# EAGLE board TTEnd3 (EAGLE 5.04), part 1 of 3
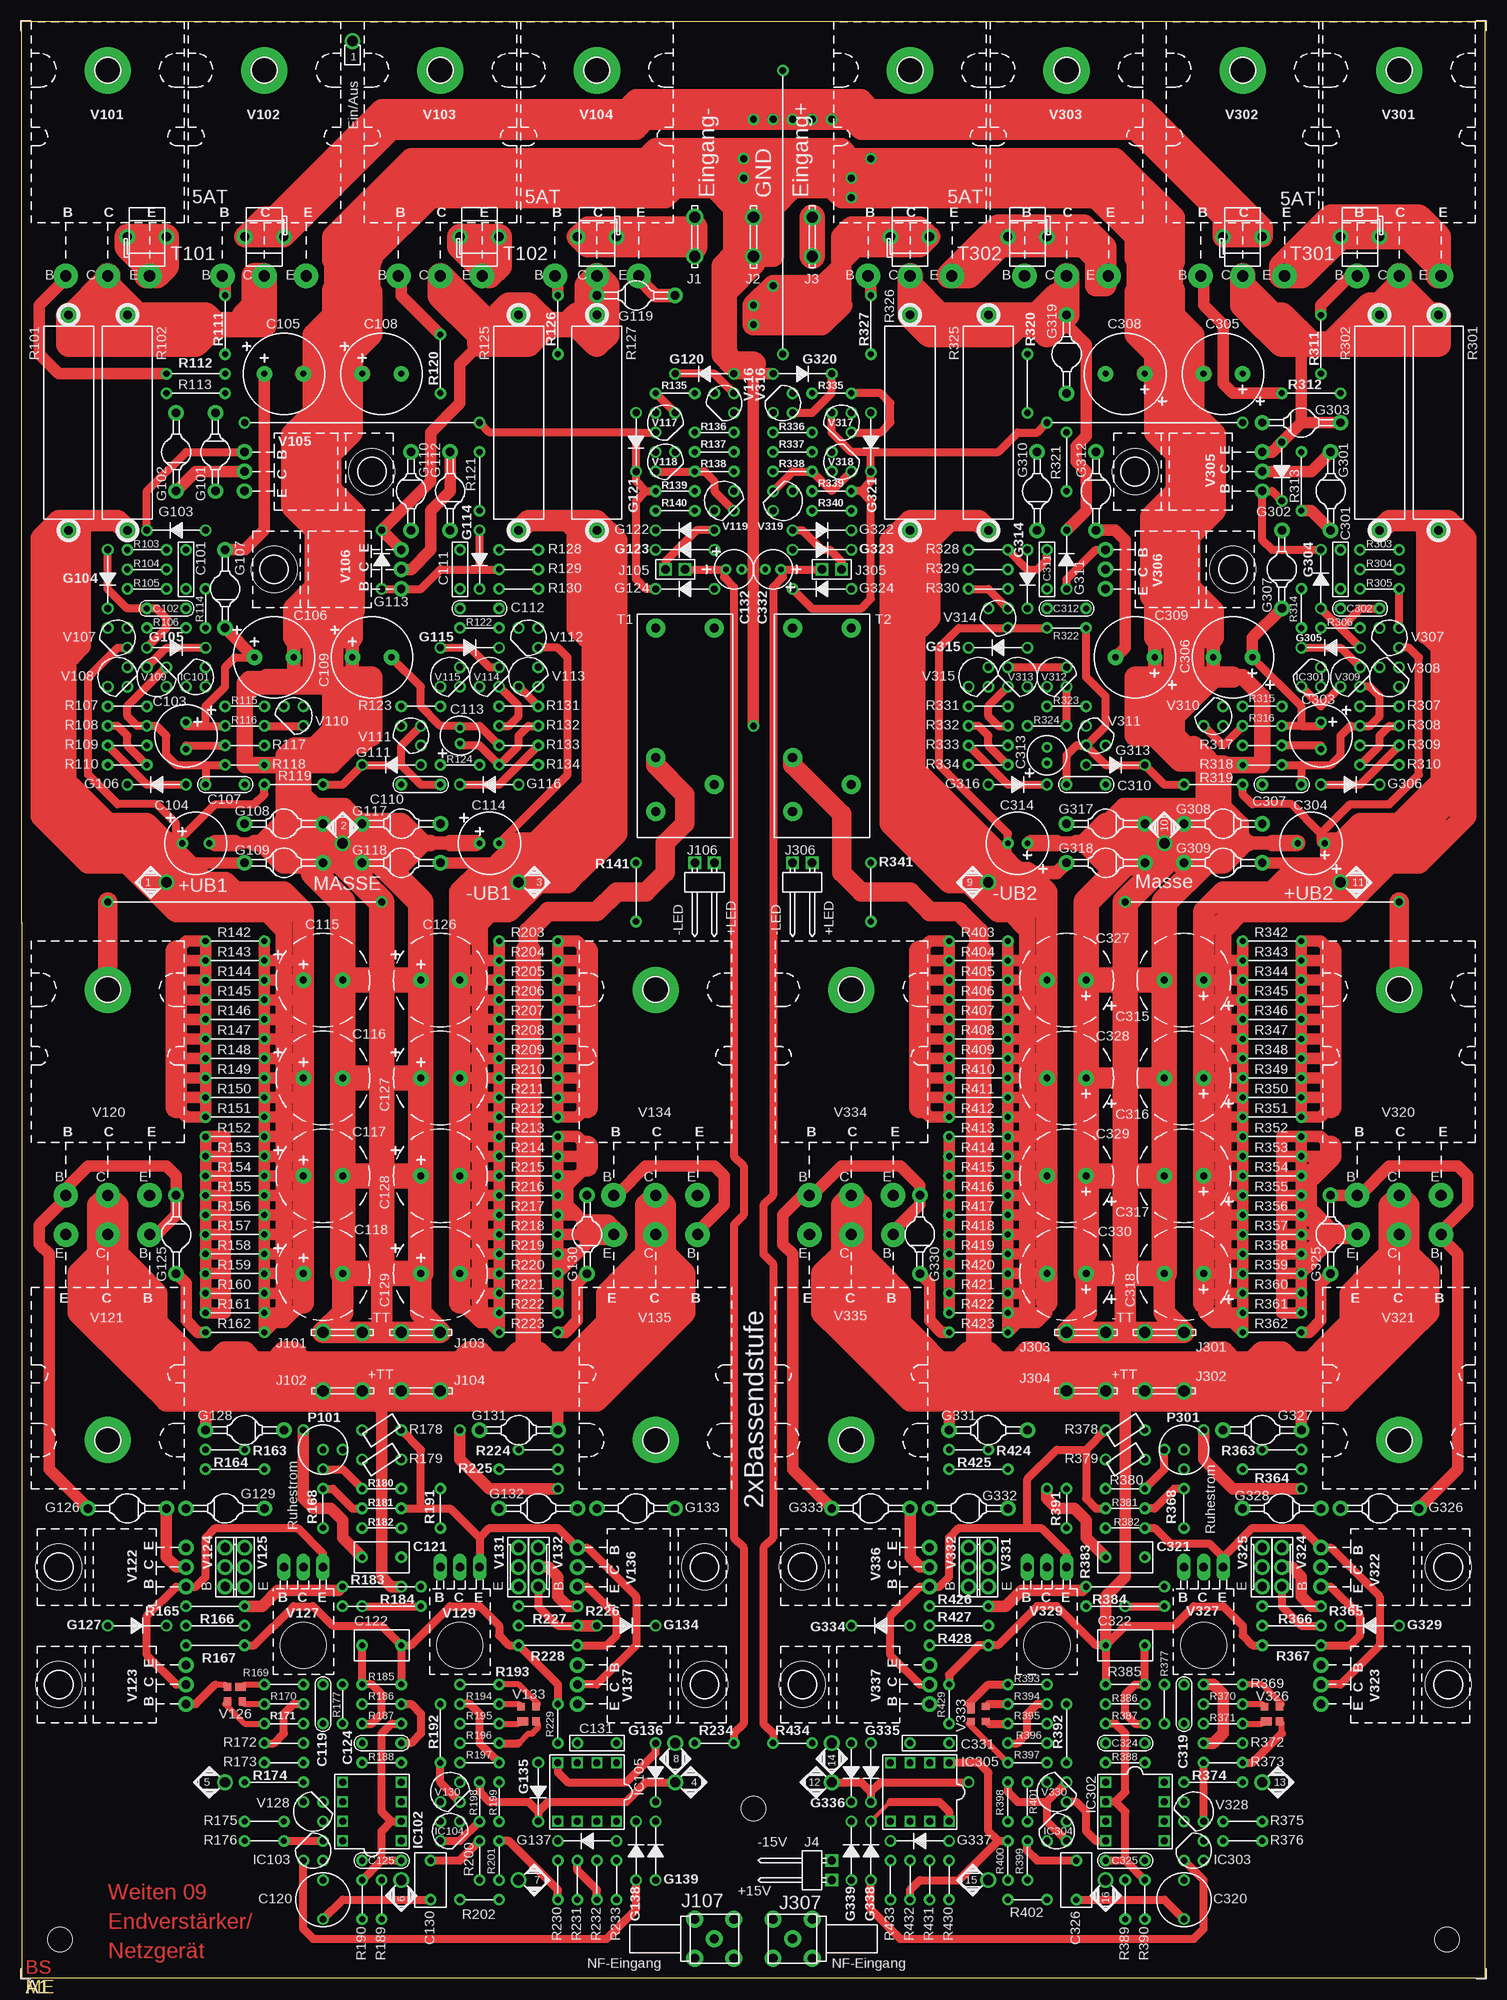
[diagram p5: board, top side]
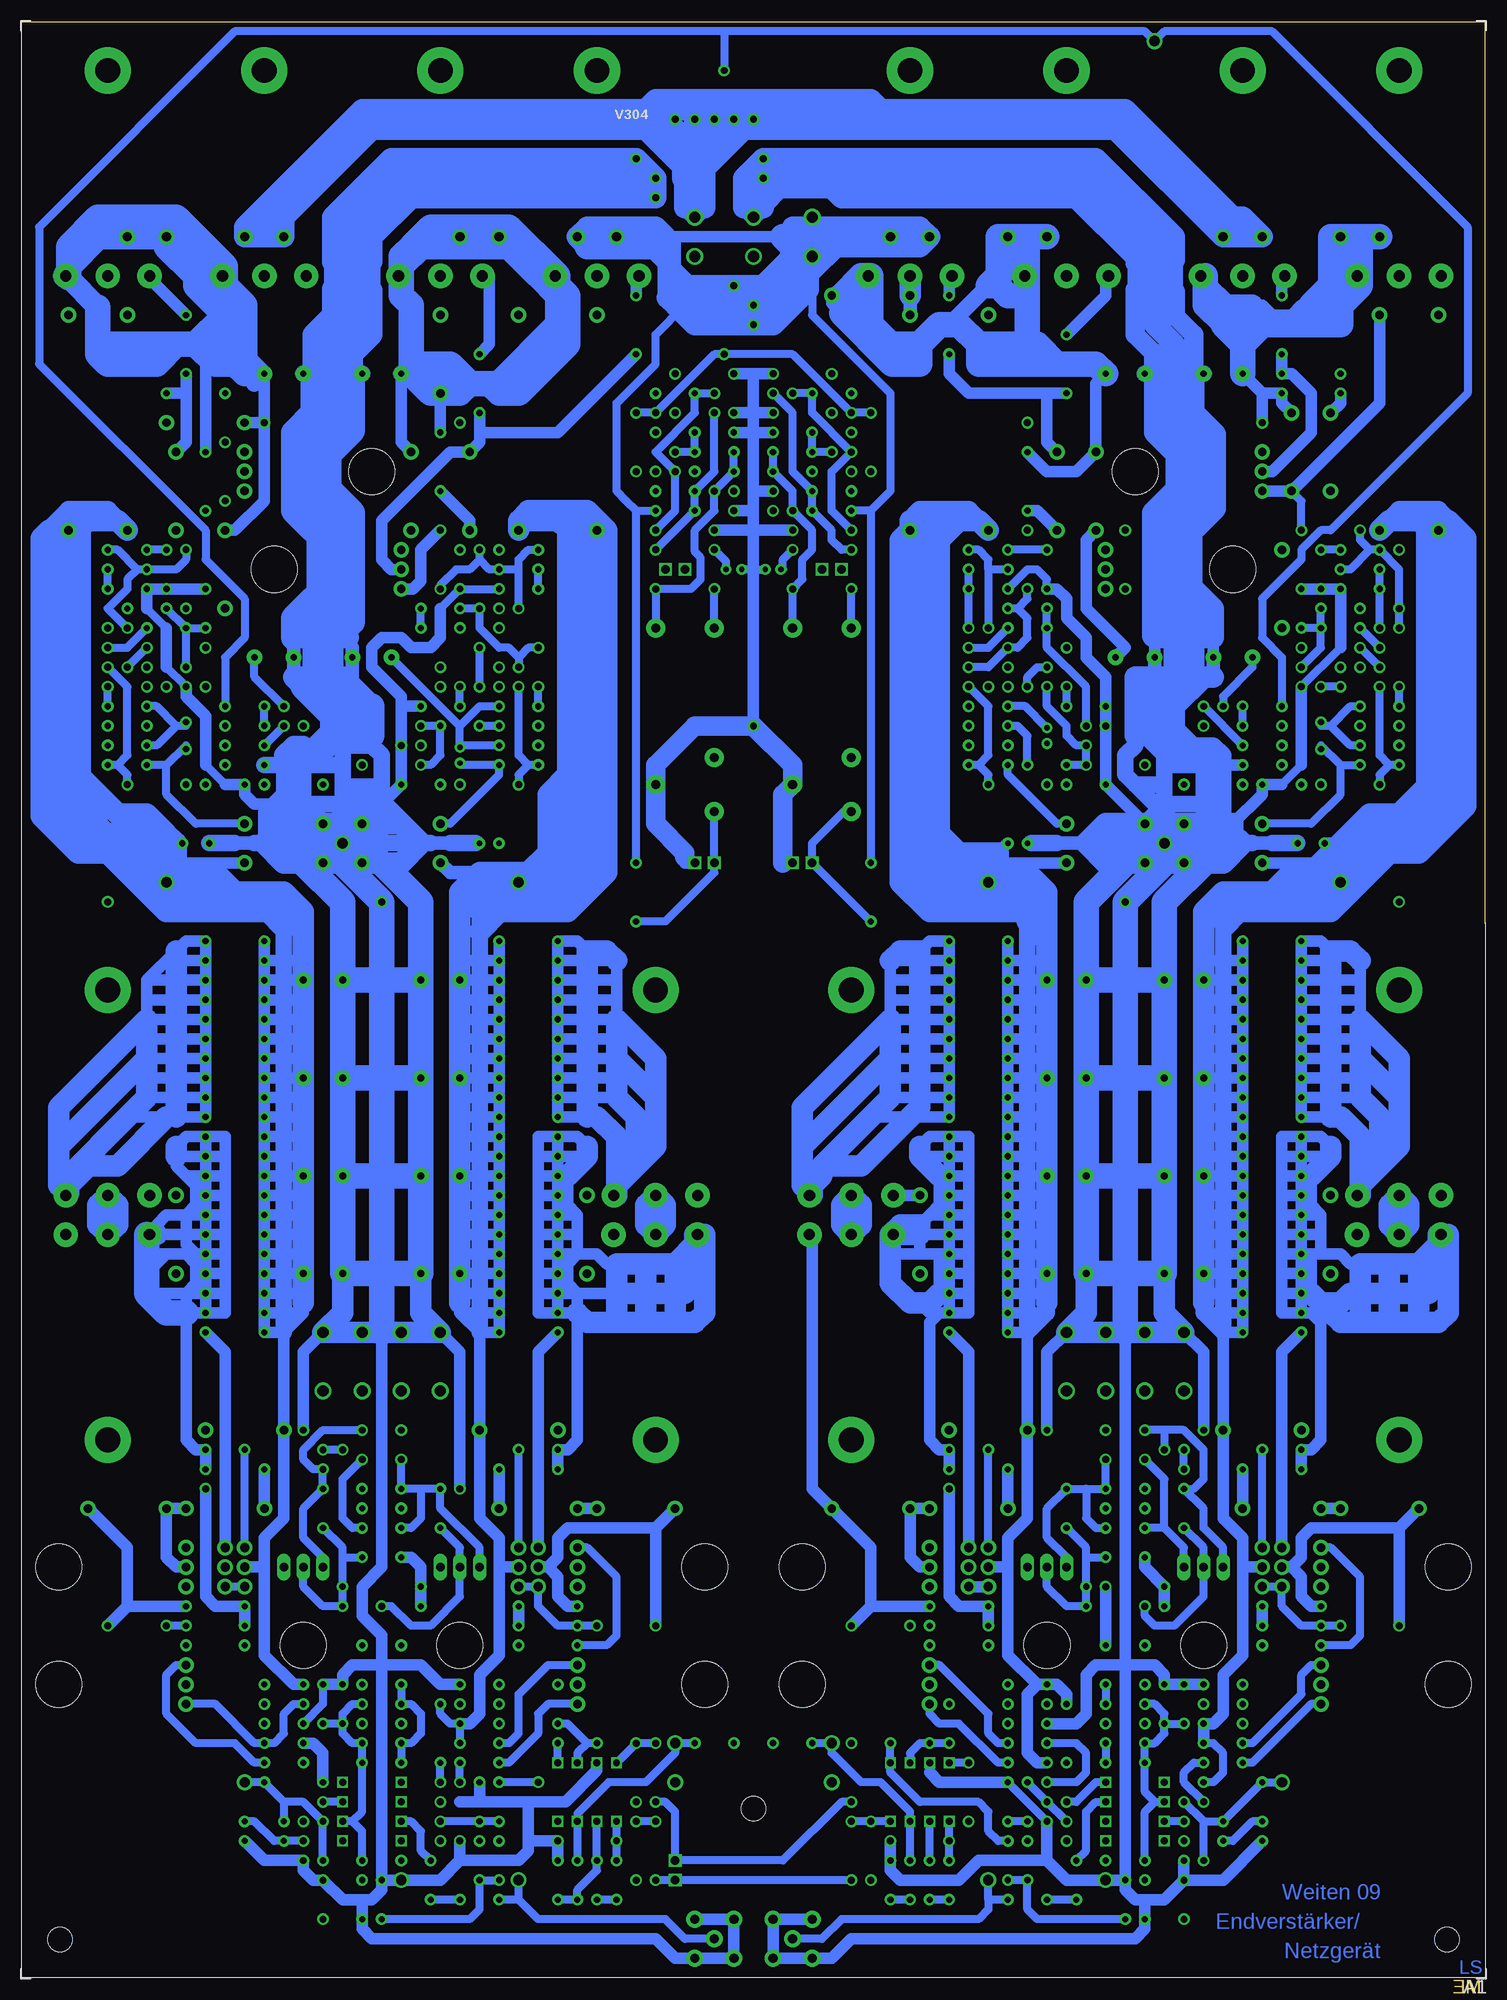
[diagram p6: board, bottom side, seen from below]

Size 190 x 254 mm. Coordinates in mm from the lower left corner, seen from the top.
Outline: 190,137.78 190,0 0,0 0,137.02
Outline: 190,137.16 190,254 0,254 0,136.91
Copper layers (1*16): Oben/V2 0.035mm / dielectric 1.5mm / Unten/V1 0.035mm
Design rules "default": minimum track width 8mil, minimum drill 24mil, track to track 20mil, track to pad 20mil, pad to pad 20mil, via to via 20mil, smd to smd 20mil, copper to edge 20mil, drill to drill 20mil, minimum pad ring 10mil, minimum via ring 8mil, stop-mask expansion 5mil, vias tented up to drill 0mil, thermal gap 10mil
Holes 6 mm at 185.17,53.34 101.35,53.34 4.83,53.34 88.65,53.34 101.35,38.1 88.65,38.1 185.17,38.1 4.83,38.1 45.47,195.58 32.77,182.88 144.53,195.58 157.23,182.88

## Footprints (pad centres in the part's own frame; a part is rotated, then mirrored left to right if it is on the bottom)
M05T2,5 = drill 0.8 pad 1.499 round: 1 -2.54,0; 2 2.54,0
K5 = drill 0.8 pad 1.499 round: 1 -2.54,0; 2 2.54,0
E3,5S08 = drill 0.8 pad 1.499 round: 1 -1.753,0; 2 1.753,0
E05S10,5 = drill 0.8 pad 2.007 round: 1 -2.54,0; 2 2.54,0
E2,0S05 = drill 0.7 pad 1.397 round: 1 -1.016,0; 2 1.016,0
E2,5S08@1 = drill 0.7 pad 1.499 round: 1 -1.27,0; 2 1.27,0
E05S12,7U = drill 0.9 pad 2.007 round: 1 -2.54,0; 2 2.54,0
KP5/7 = drill 0.9 pad 1.499 round: 1 -2.54,0; 2 2.54,0
M05T4,5 = drill 0.8 pad 1.499 round: 1 -2.54,0; 2 2.54,0
E2,5S08 = drill 0.7 pad 1.499 round: 1 -1.27,0; 2 1.27,0
LÖTFA = drill 1.35 pad 2.032 round: 1 0,0
SOD-57 = drill 1.1 pad 2.007 round: 1 -5.08,0; 2 5.08,0
DIO7-5 = drill 0.9 pad 1.499 round: 1 -2.54,0; 2 5.08,0
TO-92/BC = drill 0.9 pad 1.499 round: 1 1.27,1.27; 2 1.27,-1.27; 3 -1.27,-1.27
DIL-8 = drill 0.9 pad 1.397 square: 1 0,0; 2 2.54,0; 3 5.08,0; 4 7.62,0; 5 7.62,7.62; 6 5.08,7.62; 7 2.54,7.62; 8 0,7.62
FLACH6,3 = drill 1.45 pad 2.184 round: 1 -2.54,0; 2 2.54,0
BERG02SW = drill 1.1 pad 1.499 square: 1 0,0; 2 0,2.54
BERG02SG = drill 1.1 pad 1.499 square: 1 0,0; 2 2.54,0
SMBR665 = drill 1.2 pad 2.184 round: 1 0,0; 2 -2.54,2.54; 3 -2.54,-2.54; 4 2.54,-2.54; 5 2.54,2.54
MESSPU/R = drill 1.35 pad 2.007 round: 1 0,0
T82P = drill 0.9 pad 1.499 round: 1 -2.54,0; 2 0,2.54; S 0,0
R27,5 = drill 1.1 pad 2.007 round: 1 -12.7,0; 2 15.24,0
R5 = drill 0.8 pad 1.499 round: 1 -2.54,0; 2 2.54,0
R7,5 = drill 0.8 pad 1.499 round: 1 -3.81,0; 2 3.81,0
NTC5,0B = drill 0.9 pad 1.499 round: 1 -2.54,0; 2 2.54,0
R10 = drill 0.8 pad 1.499 round: 1 -5.08,0; 2 5.08,0
TYCORT314 = drill 1.2 pad 2.489 round: 11 7.62,2.54; 12 4.12,-5.08; 14 11.12,-5.08; A1 -12.7,-5.08; A2 -12.7,2.54
SICH5*20 = drill 1.2 pad 2.032 round: 1 -10.16,0; 2 -5.08,0; 3 5.08,0; 4 10.16,0
M3 = hole 3.2: 0,0
TO-264/LU = drill 1.45 pad 3.175 round: 1 -5.45,0; 2 0,0; 3 5.43,0
TO-220/LU = drill 1.1 pad 2.007 round: 1 -2.54,0; 2 0,0; 3 2.54,0
TO-92 = drill 0.9 pad 1.499 round: 1 -1.27,-1.27; 2 1.27,-1.27; 3 1.27,1.27
SOT-54 = drill 0.9 pad 1.499 round: B 1.27,-1.27; C 1.27,1.27; E -1.27,1.27
TO-126/S = drill 1.2 pad 2.007 round: 1 -2.54,0; 2 0,0; 3 2.54,0
SOT143 = smd 1.397 x 1.016: 1 0.737,0.965 | smd 0.94 x 1.016: 2 -0.965,0.965; 3 -0.965,-0.94; 4 0.965,-0.94
TO-126/LU = drill 1.1 pad 1.778 long: 1 -2.54,0; 2 0,0; 3 2.54,0 | hole 6: 0,10.16

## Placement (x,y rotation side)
C101  22n/63  [M05T2,5]  21.34,182.88 270 top
C102  12p  [K5]  18.8,177.8 0 top
C103  220µ/25  [E3,5S08]  21.34,161.29 270 top
C104  47µ/63  [E3,5S08]  22.61,147.32 0 top
C105  100µ/63  [E05S10,5]  34.04,208.28 0 top
C106  100µ/63  [E05S10,5]  32.77,171.45 0 top
C107  10n  [K5]  26.42,154.94 0 top
C108  100µ/63  [E05S10,5]  46.74,208.28 0 top
C109  100µ/63  [E05S10,5]  45.47,171.45 0 top
C110  1,5n  [K5]  51.82,154.94 0 top
C111  10n  [M05T2,5]  56.9,182.88 90 top
C112  12p  [K5]  59.44,177.8 0 top
C113  10µ/100  [E2,0S05]  56.9,161.29 90 top
C114  47µ/63  [E2,5S08@1]  60.71,147.32 0 top
C115  470µ/63  [E05S12,7U]  39.12,129.54 0 top
C116  470µ/63  [E05S12,7U]  39.12,116.84 0 top
C117  470µ/63  [E05S12,7U]  39.12,104.14 0 top
C118  470µ/63  [E05S12,7U]  39.12,91.44 0 top
C119  1n/63  [K5]  39.12,35.56 270 top
C120  270p  [KP5/7]  39.12,10.16 90 top
C121  220p/250  [M05T4,5]  46.74,54.61 0 top
C122  330n/50  [M05T4,5]  46.74,43.18 180 top
C124  82p/100  [K5]  46.74,30.48 0 top
C125  27p  [K5]  46.74,15.24 0 top
C126  470µ/63  [E05S12,7U]  54.36,129.54 0 top
C127  470µ/63  [E05S12,7U]  54.36,116.84 0 top
C128  470µ/63  [E05S12,7U]  54.36,104.14 0 top
C129  470µ/63  [E05S12,7U]  54.36,91.44 0 top
C130  220n/63  [M05T4,5]  53.09,12.7 90 top
C131  100n/63  [M05T2,5]  74.68,30.48 0 top
C132  10µ/100  [E2,0S05]  92.46,182.88 0 top
C301  22n/63  [M05T2,5]  171.2,182.88 270 top
C302  12p  [K5]  173.74,177.8 180 top
C303  220µ/25  [E3,5S08]  168.66,161.29 270 top
C304  47µ/63  [E3,5S08]  167.39,147.32 180 top
C305  100µ/63  [E05S10,5]  155.96,208.28 180 top
C306  100µ/63  [E05S10,5]  157.23,171.45 180 top
C307  10n  [K5]  163.58,154.94 180 top
C308  100µ/63  [E05S10,5]  143.26,208.28 180 top
C309  100µ/63  [E05S10,5]  144.53,171.45 180 top
C310  1,5n  [K5]  138.18,154.94 180 top
C311  10n  [M05T2,5]  133.1,182.88 90 top
C312  12p  [K5]  135.64,177.8 180 top
C313  10µ/100  [E2,0S05]  133.1,158.75 90 top
C314  47µ/63  [E2,5S08]  129.29,147.32 180 top
C315  470µ/63  [E05S12,7U]  150.88,129.54 180 top
C316  470µ/63  [E05S12,7U]  150.88,116.84 180 top
C317  470µ/63  [E05S12,7U]  150.88,104.14 180 top
C318  470µ/63  [E05S12,7U]  150.88,91.44 180 top
C319  330p  [K5]  150.88,35.56 270 top
C320  270p  [KP5/7]  150.88,10.16 90 top
C321  220p/250  [M05T4,5]  143.26,54.61 0 top
C322  330n  [M05T4,5]  143.26,43.18 0 top
C324  82p/100  [K5]  143.26,30.48 180 top
C325  27p  [K5]  143.26,15.24 180 top
C326  220n/63  [M05T4,5]  136.91,12.7 90 top
C327  470µ/63  [E05S12,7U]  135.64,129.54 180 top
C328  470µ/63  [E05S12,7U]  135.64,116.84 180 top
C329  470µ/63  [E05S12,7U]  135.64,104.14 180 top
C330  470µ/63  [E05S12,7U]  135.64,91.44 180 top
C331  100n/63  [M05T2,5]  117.86,30.48 0 top
C332  10µ/100  [E2,0S05]  97.54,182.88 180 top
EIN1  1  [LÖTFA]  42.93,251.46 90 top
G101  BYV27  [SOD-57]  25.15,198.12 90 top
G102  BYV27  [SOD-57]  20.07,198.12 270 top
G103  1N4148  [DIO7-5]  21.34,187.96 180 top
G104  1N4148  [DIO7-5]  11.18,182.88 270 top
G105  1N4148  [DIO7-5]  18.8,172.72 0 top
G106  1N4148  [DIO7-5]  18.8,154.94 180 top
G107  BYV27  [SOD-57]  26.42,180.34 270 top
G108  BYV27  [SOD-57]  34.04,149.86 180 top
G109  BYV27  [SOD-57]  34.04,144.78 180 top
G110  BYV27  [SOD-57]  50.55,193.04 90 top
G111  1N4148  [DIO7-5]  49.28,157.48 180 top
G112  BYV27  [SOD-57]  55.63,193.04 270 top
G113  1N4148  [DIO7-5]  46.74,182.88 90 top
G114  1N4148  [DIO7-5]  59.44,185.42 270 top
G115  1N4148  [DIO7-5]  56.9,172.72 0 top
G116  1N4148  [DIO7-5]  61.98,154.94 180 top
G117  BYV27  [SOD-57]  49.28,149.86 180 top
G118  BYV27  [SOD-57]  49.28,144.78 180 top
G119  BYV27  [SOD-57]  79.76,218.44 180 top
G120  1N4148  [DIO7-5]  89.92,208.28 180 top
G121  1N4148  [DIO7-5]  79.76,200.66 270 top
G122  1N4148  [DIO7-5]  87.38,187.96 180 top
G123  1N4148  [DIO7-5]  87.38,185.42 180 top
G124  1N4148  [DIO7-5]  87.38,180.34 180 top
G125  BYV27  [SOD-57]  20.07,96.52 90 top
G126  BYV27  [SOD-57]  13.72,60.96 0 top
G127  BAT41  [DIO7-5]  13.72,45.72 0 top
G128  BYV27  [SOD-57]  28.96,71.12 0 top
G129  BYV27  [SOD-57]  26.42,60.96 180 top
G130  BYV27  [SOD-57]  73.41,96.52 270 top
G131  BYV27  [SOD-57]  64.52,71.12 0 top
G132  BYV27  [SOD-57]  67.06,60.96 180 top
G133  BYV27  [SOD-57]  79.76,60.96 0 top
G134  BAT41  [DIO7-5]  77.22,45.72 0 top
G135  1N4148  [DIO7-5]  67.06,25.4 270 top
G136  1N4148  [DIO7-5]  82.3,27.94 270 top
G137  1N4148  [DIO7-5]  74.68,17.78 180 top
G138  1N4148  [DIO7-5]  79.76,15.24 90 top
G139  1N4148  [DIO7-5]  82.3,15.24 90 top
G301  BYV27  [SOD-57]  169.93,193.04 90 top
G302  1N4148  [DIO7-5]  163.58,196.85 270 top
G303  BYV27  [SOD-57]  166.12,201.93 180 top
G304  1N4148  [DIO7-5]  168.66,180.34 90 top
G305  1N4148  [DIO7-5]  171.2,172.72 180 top
G306  1N4148  [DIO7-5]  171.2,154.94 0 top
G307  BYV27  [SOD-57]  163.58,182.88 270 top
G308  BYV27  [SOD-57]  155.96,149.86 0 top
G309  BYV27  [SOD-57]  155.96,144.78 0 top
G310  BYV27  [SOD-57]  131.83,193.04 270 top
G311  1N4148  [DIO7-5]  135.64,182.88 90 top
G312  BYV27  [SOD-57]  139.45,193.04 90 top
G313  1N4148  [DIO7-5]  140.72,157.48 0 top
G314  1N4148  [DIO7-5]  130.56,182.88 270 top
G315  1N4148  [DIO7-5]  128.02,172.72 180 top
G316  1N4148  [DIO7-5]  128.02,154.94 0 top
G317  BYV27  [SOD-57]  140.72,149.86 0 top
G318  BYV27  [SOD-57]  140.72,144.78 0 top
G319  BYV27  [SOD-57]  135.64,210.82 90 top
G320  1N4148  [DIO7-5]  100.08,208.28 0 top
G321  1N4148  [DIO7-5]  110.24,200.66 270 top
G322  1N4148  [DIO7-5]  102.62,187.96 0 top
G323  1N4148  [DIO7-5]  102.62,185.42 0 top
G324  1N4148  [DIO7-5]  105.16,180.34 180 top
G325  BYV27  [SOD-57]  169.93,96.52 90 top
G326  BYV27  [SOD-57]  176.28,60.96 180 top
G327  BYV27  [SOD-57]  161.04,71.12 180 top
G328  BYV27  [SOD-57]  163.58,60.96 0 top
G329  BAT41  [DIO7-5]  176.28,45.72 180 top
G330  BYV27  [SOD-57]  116.59,96.52 270 top
G331  BYV27  [SOD-57]  125.48,71.12 180 top
G332  BYV27  [SOD-57]  122.94,60.96 0 top
G333  BYV27  [SOD-57]  110.24,60.96 180 top
G334  BAT41  [DIO7-5]  112.78,45.72 180 top
G335  1N4148  [DIO7-5]  110.24,27.94 270 top
G336  1N4148  [DIO7-5]  107.7,27.94 270 top
G337  1N4148  [DIO7-5]  117.86,17.78 180 top
G338  1N4148  [DIO7-5]  110.24,15.24 90 top
G339  1N4148  [DIO7-5]  107.7,15.24 90 top
IC101  TL431  [TO-92/BC]  22.61,168.91 0 top
IC102  OPA134  [DIL-8]  49.28,17.78 90 top
IC103  TL431  [TO-92/BC]  37.85,16.51 0 top
IC104  TL431  [TO-92/BC]  55.63,19.05 180 top
IC105  TL062  [DIL-8]  77.22,27.94 180 top
IC301  TL431  [TO-92/BC]  167.39,168.91 0 top
IC302  OPA134  [DIL-8]  140.72,25.4 270 top
IC303  TL431  [TO-92/BC]  152.15,16.51 0 top
IC304  TL431  [TO-92/BC]  134.37,19.05 0 top
IC305  TL062  [DIL-8]  120.4,27.94 180 top
J1  FLACH6,3  [FLACH6,3]  87.38,226.06 270 top
J2  FLACH6,3  [FLACH6,3]  95,226.06 90 top
J3  FLACH6,3  [FLACH6,3]  102.62,226.06 270 top
J4  BERG02SW  [BERG02SW]  105.16,12.7 0 top
J101  FLACH6,3  [FLACH6,3]  41.66,83.82 0 top
J102  FLACH6,3  [FLACH6,3]  41.66,76.2 180 top
J103  FLACH6,3  [FLACH6,3]  51.82,83.82 0 top
J104  FLACH6,3  [FLACH6,3]  51.82,76.2 180 top
J105  BERG02SG  [BERG02SG]  86.11,182.88 180 top
J106  BERG02SW  [BERG02SW]  89.92,144.78 90 top
J107  SMB  [SMBR665]  89.92,5.08 180 top
J301  FLACH6,3  [FLACH6,3]  148.34,83.82 180 top
J302  FLACH6,3  [FLACH6,3]  148.34,76.2 0 top
J303  FLACH6,3  [FLACH6,3]  138.18,83.82 0 top
J304  FLACH6,3  [FLACH6,3]  138.18,76.2 0 top
J305  BERG02SG  [BERG02SG]  103.89,182.88 0 top
J306  BERG02SW  [BERG02SW]  102.62,144.78 90 top
J307  SMB  [SMBR665]  100.08,5.08 0 top
MP1  1  [MESSPU/R]  18.8,142.24 0 top
MP2  3  [MESSPU/R]  64.52,142.24 180 top
MP3  2  [MESSPU/R]  41.66,147.32 270 top
MP4  9  [MESSPU/R]  125.48,142.24 0 top
MP5  10  [MESSPU/R]  148.34,147.32 270 top
MP6  11  [MESSPU/R]  171.2,142.24 180 top
MP7  7  [MESSPU/R]  64.52,12.7 180 top
MP8  15  [MESSPU/R]  125.48,12.7 0 top
MP9  13  [MESSPU/R]  161.04,25.4 180 top
MP10  12  [MESSPU/R]  105.16,25.4 0 top
MP11  5  [MESSPU/R]  26.42,25.4 0 top
MP12  4  [MESSPU/R]  84.84,25.4 180 top
MP13  6  [MESSPU/R]  49.28,12.7 90 top
MP14  16  [MESSPU/R]  140.72,12.7 90 top
MP15  8  [MESSPU/R]  84.84,30.48 90 top
MP16  14  [MESSPU/R]  105.16,30.48 90 top
P101  500  [T82P]  39.12,68.58 180 top
P301  500  [T82P]  150.88,68.58 90 top
R101  0,1  [R27,5]  6.1,203.2 270 top
R102  0,1  [R27,5]  13.72,203.2 270 top
R103  220  [R5]  16.26,185.42 0 top
R104  430  [R5]  16.26,182.88 180 top
R105  18k  [R5]  16.26,180.34 0 top
R106  39k  [R5]  18.8,175.26 0 top
R107  100  [R5]  13.72,165.1 180 top
R108  33k  [R5]  13.72,162.56 0 top
R109  510  [R5]  13.72,160.02 180 top
R110  8,2k  [R5]  13.72,157.48 0 top
R111  3,3  [R7,5]  26.42,214.63 90 top
R112  3,3  [R7,5]  22.61,208.28 180 top
R113  100  [R7,5]  22.61,205.74 180 top
R114  2,7k  [R5]  23.88,177.8 90 top
R115  47k  [R5]  28.96,165.1 180 top
R116  22k  [R5]  28.96,162.56 0 top
R117  100  [R5]  28.96,160.02 180 top
R118  4,7k  [R5]  28.96,157.48 0 top
R119  33k  [R7,5]  35.31,154.94 0 top
R120  3,3  [R7,5]  54.36,209.55 90 top
R121  100  [R7,5]  59.44,194.31 90 top
R122  33k  [R5]  59.44,175.26 0 top
R123  2,2  [R5]  51.82,165.1 0 top
R124  3,9k  [R5]  56.9,157.48 0 top
R125  0,1  [R27,5]  64.52,200.66 90 top
R126  3,3  [R7,5]  69.6,214.63 90 top
R127  0,1  [R27,5]  74.68,200.66 90 top
R128  1k  [R5]  64.52,185.42 0 top
R129  430  [R5]  64.52,182.88 180 top
R130  18k  [R5]  64.52,180.34 0 top
R131  100  [R5]  64.52,165.1 180 top
R132  33k  [R5]  64.52,162.56 0 top
R133  510  [R5]  64.52,160.02 180 top
R134  8,2k  [R5]  64.52,157.48 0 top
R135  1,2M  [R5]  84.84,205.74 0 top
R136  1k  [R5]  89.92,200.66 0 top
R137  47k  [R5]  89.92,198.12 180 top
R138  22k  [R5]  89.92,195.58 180 top
R139  1,2M  [R5]  84.84,193.04 180 top
R140  470K  [R5]  84.84,190.5 180 top
R141  15k  [R7,5]  79.76,140.97 270 top
R142  2,2  [R7,5]  27.69,134.62 180 top
R143  2,2  [R7,5]  27.69,132.08 180 top
R144  2,2  [R7,5]  27.69,129.54 0 top
R145  2,2  [R7,5]  27.69,127 180 top
R146  2,2  [R7,5]  27.69,124.46 180 top
R147  2,2  [R7,5]  27.69,121.92 0 top
R148  2,2  [R7,5]  27.69,119.38 0 top
R149  2,2  [R7,5]  27.69,116.84 0 top
R150  2,2  [R7,5]  27.69,114.3 180 top
R151  2,2  [R7,5]  27.69,111.76 0 top
R152  2,2  [R7,5]  27.69,109.22 0 top
R153  2,2  [R7,5]  27.69,106.68 0 top
R154  2,2  [R7,5]  27.69,104.14 0 top
R155  2,2  [R7,5]  27.69,101.6 0 top
R156  2,2  [R7,5]  27.69,99.06 0 top
R157  2,2  [R7,5]  27.69,96.52 0 top
R158  2,2  [R7,5]  27.69,93.98 0 top
R159  2,2  [R7,5]  27.69,91.44 0 top
R160  2,2  [R7,5]  27.69,88.9 0 top
R161  2,2  [R7,5]  27.69,86.36 0 top
R162  15  [R7,5]  27.69,83.82 180 top
R163  100  [R5]  26.42,68.58 180 top
R164  33  [R7,5]  27.69,66.04 0 top
R165  18k  [R7,5]  25.15,48.26 0 top
R166  12k  [R7,5]  25.15,45.72 0 top
R167  1  [R7,5]  25.15,43.18 0 top
R168  680  [R5]  39.12,60.96 270 top
R169  33k  [R5]  34.04,38.1 0 top
R170  100  [R5]  34.04,35.56 0 top
R171  120  [R5]  34.04,33.02 180 top
R172  33  [R5]  34.04,30.48 180 top
R173  330  [R5]  34.04,27.94 0 top
R174  6,8k  [R7,5]  32.77,25.4 180 top
R175  12k  [R5]  31.5,20.32 180 top
R176  2,7k  [R5]  31.5,17.78 180 top
R177  1k  [R5]  41.66,35.56 270 top
R178  3,3k  [NTC5,0B]  46.74,71.12 0 top
R179  3,3k  [NTC5,0B]  46.74,67.31 0 top
R180  100  [R5]  46.74,63.5 0 top
R181  1,5k  [R5]  46.74,60.96 0 top
R182  1,5k  [R5]  46.74,58.42 0 top
R183  5,6k  [R10]  46.74,50.8 0 top
R184  5,6k  [R10]  46.74,48.26 0 top
R185  180k  [R5]  46.74,38.1 180 top
R186  8,2k  [R5]  46.74,35.56 0 top
R187  47k  [R5]  46.74,33.02 180 top
R188  7,5k  [R5]  46.74,27.94 0 top
R189  1,5k  [R5]  46.74,10.16 270 top
R190  2,2k  [R5]  44.2,10.16 270 top
R191  680  [R5]  54.36,60.96 270 top
R192  6,8k  [R7,5]  54.36,31.75 90 top
R193  120  [R5]  59.44,38.1 180 top
R194  100  [R5]  59.44,35.56 180 top
R195  33k  [R5]  59.44,33.02 0 top
R196  330  [R5]  59.44,30.48 0 top
R197  33  [R5]  59.44,27.94 180 top
R198  2,7k  [R5]  59.44,22.86 90 top
R199  12k  [R5]  61.98,22.86 270 top
R200  47k  [R5]  59.44,15.24 270 top
R201  220k  [R5]  61.98,15.24 90 top
R202  2,2k  [R5]  59.44,10.16 180 top
R203  2,2  [R7,5]  65.79,134.62 180 top
R204  2,2  [R7,5]  65.79,132.08 180 top
R205  2,2  [R7,5]  65.79,129.54 180 top
R206  2,2  [R7,5]  65.79,127 0 top
R207  2,2  [R7,5]  65.79,124.46 180 top
R208  2,2  [R7,5]  65.79,121.92 0 top
R209  2,2  [R7,5]  65.79,119.38 180 top
R210  2,2  [R7,5]  65.79,116.84 0 top
R211  2,2  [R7,5]  65.79,114.3 0 top
R212  2,2  [R7,5]  65.79,111.76 0 top
R213  2,2  [R7,5]  65.79,109.22 180 top
R214  2,2  [R7,5]  65.79,106.68 180 top
R215  2,2  [R7,5]  65.79,104.14 180 top
R216  2,2  [R7,5]  65.79,101.6 180 top
R217  2,2  [R7,5]  65.79,99.06 180 top
R218  2,2  [R7,5]  65.79,96.52 180 top
R219  2,2  [R7,5]  65.79,93.98 180 top
R220  2,2  [R7,5]  65.79,91.44 180 top
R221  2,2  [R7,5]  65.79,88.9 180 top
R222  2,2  [R7,5]  65.79,86.36 180 top
R223  15  [R7,5]  65.79,83.82 180 top
R224  100  [R5]  67.06,68.58 0 top
R225  33  [R7,5]  65.79,66.04 0 top
R226  18k  [R7,5]  68.33,48.26 0 top
R227  12k  [R7,5]  68.33,45.72 0 top
R228  1  [R7,5]  68.33,43.18 0 top
R229  2,2M  [R5]  69.6,33.02 90 top
R230  220k  [R5]  69.6,12.7 270 top
R231  220k  [R5]  72.14,12.7 270 top
R232  220k  [R5]  74.68,12.7 270 top
R233  1M  [R5]  77.22,12.7 90 top
R234  100k  [R5]  89.92,30.48 0 top
R301  0,1  [R27,5]  183.9,203.2 270 top
R302  0,1  [R27,5]  176.28,203.2 270 top
R303  220  [R5]  176.28,185.42 180 top
R304  430  [R5]  176.28,182.88 0 top
R305  18k  [R5]  176.28,180.34 180 top
R306  39k  [R5]  171.2,175.26 180 top
R307  100  [R5]  176.28,165.1 0 top
R308  33k  [R5]  176.28,162.56 180 top
R309  510  [R5]  176.28,160.02 0 top
R310  8,2k  [R5]  176.28,157.48 180 top
R311  3,3  [R7,5]  168.66,212.09 90 top
R312  3,3  [R7,5]  167.39,205.74 180 top
R313  100  [R7,5]  166.12,194.31 270 top
R314  2,7k  [R5]  166.12,177.8 90 top
R315  47k  [R5]  161.04,165.1 0 top
R316  22k  [R5]  161.04,162.56 180 top
R317  100  [R5]  161.04,160.02 0 top
R318  4,7k  [R5]  161.04,157.48 180 top
R319  33k  [R7,5]  154.69,154.94 180 top
R320  3,3  [R7,5]  130.56,207.01 90 top
R321  100  [R7,5]  135.64,196.85 90 top
R322  33k  [R5]  135.64,175.26 180 top
R323  2,2  [R5]  135.64,165.1 180 top
R324  3,9k  [R5]  133.1,162.56 180 top
R325  0,1  [R27,5]  125.48,200.66 90 top
R326  0,1  [R27,5]  115.32,200.66 90 top
R327  3,3  [R7,5]  110.24,214.63 90 top
R328  1k  [R5]  125.48,185.42 180 top
R329  430  [R5]  125.48,182.88 0 top
R330  18k  [R5]  125.48,180.34 180 top
R331  100  [R5]  125.48,165.1 0 top
R332  33k  [R5]  125.48,162.56 180 top
R333  510  [R5]  125.48,160.02 0 top
R334  8,2k  [R5]  125.48,157.48 180 top
R335  1,2M  [R5]  105.16,205.74 0 top
R336  1k  [R5]  100.08,200.66 180 top
R337  47k  [R5]  100.08,198.12 0 top
R338  22k  [R5]  100.08,195.58 0 top
R339  1,2M  [R5]  105.16,193.04 180 top
R340  470k  [R5]  105.16,190.5 0 top
R341  15k  [R7,5]  110.24,140.97 270 top
R342  2,2  [R7,5]  162.31,134.62 0 top
R343  2,2  [R7,5]  162.31,132.08 0 top
R344  2,2  [R7,5]  162.31,129.54 180 top
R345  2,2  [R7,5]  162.31,127 0 top
R346  2,2  [R7,5]  162.31,124.46 0 top
R347  2,2  [R7,5]  162.31,121.92 180 top
R348  2,2  [R7,5]  162.31,119.38 180 top
R349  2,2  [R7,5]  162.31,116.84 180 top
R350  2,2  [R7,5]  162.31,114.3 0 top
R351  2,2  [R7,5]  162.31,111.76 180 top
R352  2,2  [R7,5]  162.31,109.22 180 top
R353  2,2  [R7,5]  162.31,106.68 180 top
R354  2,2  [R7,5]  162.31,104.14 180 top
R355  2,2  [R7,5]  162.31,101.6 180 top
R356  2,2  [R7,5]  162.31,99.06 180 top
R357  2,2  [R7,5]  162.31,96.52 180 top
R358  2,2  [R7,5]  162.31,93.98 180 top
R359  2,2  [R7,5]  162.31,91.44 180 top
R360  2,2  [R7,5]  162.31,88.9 180 top
R361  2,2  [R7,5]  162.31,86.36 180 top
R362  15  [R7,5]  162.31,83.82 0 top
R363  100  [R5]  163.58,68.58 0 top
R364  33  [R7,5]  162.31,66.04 180 top
R365  18k  [R7,5]  164.85,48.26 180 top
R366  12k  [R7,5]  164.85,45.72 180 top
R367  1  [R7,5]  164.85,43.18 180 top
R368  680  [R5]  150.88,60.96 270 top
R369  120  [R5]  155.96,38.1 0 top
R370  100  [R5]  155.96,35.56 180 top
R371  33k  [R5]  155.96,33.02 180 top
R372  33  [R5]  155.96,30.48 0 top
R373  330  [R5]  155.96,27.94 180 top
R374  6,8k  [R7,5]  154.69,25.4 0 top
R375  12k  [R5]  158.5,20.32 0 top
R376  2,7k  [R5]  158.5,17.78 0 top
R377  1k  [R5]  148.34,35.56 270 top
R378  3,3k  [NTC5,0B]  143.26,71.12 180 top
R379  3,3k  [NTC5,0B]  143.26,67.31 180 top
R380  100  [R5]  143.26,63.5 180 top
R381  1,5k  [R5]  143.26,60.96 180 top
R382  1,5k  [R5]  143.26,58.42 180 top
R383  5,6k  [R10]  143.26,50.8 0 top
R384  5,6k  [R10]  143.26,48.26 0 top
R385  180k  [R5]  143.26,38.1 0 top
R386  8,2k  [R5]  143.26,35.56 180 top
R387  47k  [R5]  143.26,33.02 0 top
R388  7,5k  [R5]  143.26,27.94 180 top
R389  1,5k  [R5]  143.26,10.16 270 top
R390  2,2k  [R5]  145.8,10.16 270 top
R391  680  [R5]  135.64,60.96 270 top
R392  6,8k  [R7,5]  135.64,31.75 90 top
R393  33k  [R5]  130.56,38.1 180 top
R394  100  [R5]  130.56,35.56 0 top
R395  120  [R5]  130.56,33.02 0 top
R396  33  [R5]  130.56,30.48 0 top
R397  330  [R5]  130.56,27.94 180 top
R398  2,7k  [R5]  128.02,22.86 90 top
R399  47k  [R5]  130.56,15.24 270 top
R400  220k  [R5]  128.02,15.24 90 top
R401  12k  [R5]  130.56,22.86 270 top
R402  2,2k  [R5]  130.56,10.16 0 top
R403  2,2  [R7,5]  124.21,134.62 0 top
R404  2,2  [R7,5]  124.21,132.08 0 top
R405  2,2  [R7,5]  124.21,129.54 0 top
R406  2,2  [R7,5]  124.21,127 180 top
R407  2,2  [R7,5]  124.21,124.46 0 top
R408  2,2  [R7,5]  124.21,121.92 180 top
R409  2,2  [R7,5]  124.21,119.38 0 top
R410  2,2  [R7,5]  124.21,116.84 180 top
R411  2,2  [R7,5]  124.21,114.3 180 top
R412  2,2  [R7,5]  124.21,111.76 180 top
R413  2,2  [R7,5]  124.21,109.22 0 top
R414  2,2  [R7,5]  124.21,106.68 0 top
R415  2,2  [R7,5]  124.21,104.14 0 top
R416  2,2  [R7,5]  124.21,101.6 0 top
R417  2,2  [R7,5]  124.21,99.06 0 top
R418  2,2  [R7,5]  124.21,96.52 0 top
R419  2,2  [R7,5]  124.21,93.98 0 top
R420  2,2  [R7,5]  124.21,91.44 0 top
R421  2,2  [R7,5]  124.21,88.9 0 top
R422  2,2  [R7,5]  124.21,86.36 0 top
R423  15  [R7,5]  124.21,83.82 0 top
R424  100  [R5]  122.94,68.58 180 top
R425  33  [R7,5]  124.21,66.04 180 top
R426  18k  [R7,5]  121.67,48.26 180 top
R427  12k  [R7,5]  121.67,45.72 180 top
R428  1  [R7,5]  121.67,43.18 180 top
R429  2,2M  [R5]  120.4,35.56 90 top
R430  1M  [R5]  120.4,12.7 90 top
R431  220k  [R5]  117.86,12.7 270 top
R432  220k  [R5]  115.32,12.7 270 top
R433  220k  [R5]  112.78,12.7 270 top
R434  100k  [R5]  100.08,30.48 180 top
T1  TYCORT314  [TYCORT314]  87.38,162.56 270 top
T2  TYCORT314  [TYCORT314]  105.16,162.56 270 top
T101  5AT  [SICH5*20]  23.88,226.06 180 top
T102  5AT  [SICH5*20]  67.06,226.06 180 top
T301  5AT  [SICH5*20]  166.12,226.06 0 top
T302  5AT  [SICH5*20]  122.94,226.06 0 top
U$4  [M3]  185,5 90 bottom
U$35  [M3]  95,22 90 top
U$36  [M3]  5,5 90 top
U$37  [ECKE/A]  190,254 180 top
U$38  [ECKE/A]  0,254 270 top
U$40  [ECKE/A]  0,0 0 top
U$56  [A/BEZUG]  0.51,0.51 0 top
U$161  [ECKE/A]  190,0 90 top
V101  MJL1302A  [TO-264/LU]  11.18,220.98 0 top
V102  MJL1302A  [TO-264/LU]  31.5,220.98 0 top
V103  MJL3281A  [TO-264/LU]  54.36,220.98 0 top
V104  MJL3281A  [TO-264/LU]  74.68,220.98 0 top
V105  MJE15028  [TO-220/LU]  28.96,195.58 270 top
V106  MJE15029  [TO-220/LU]  49.28,182.88 90 top
V107  BC549C  [TO-92/BC]  12.45,173.99 90 top
V108  2N5401  [TO-92]  12.45,168.91 0 top
V109  2N5551  [TO-92]  17.53,168.91 90 top
V110  BC369  [SOT-54]  35.31,163.83 0 top
V111  BC549C  [TO-92/BC]  50.55,161.29 90 top
V112  BC559C  [TO-92/BC]  65.79,173.99 90 top
V113  2N5551  [TO-92]  65.79,168.91 0 top
V114  2N5401  [TO-92]  60.71,168.91 0 top
V115  2N3906  [TO-92]  55.63,168.91 0 top
V116  BC549C  [TO-92/BC]  91.19,204.47 90 top
V117  BC546B  [TO-92/BC]  83.57,201.93 180 top
V118  BC546B  [TO-92/BC]  83.57,196.85 180 top
V119  2N5401  [TO-92]  91.19,191.77 0 top
V120  MJL1302A  [TO-264/LU]  11.18,101.6 0 top
V121  MJL1302A  [TO-264/LU]  11.18,96.52 180 top
V122  MJE15030  [TO-220/LU]  21.34,53.34 90 top
V123  MJE15031  [TO-220/LU]  21.34,38.1 90 top
V124  BD140S  [TO-126/S]  26.42,53.34 270 top
V125  BD139S  [TO-126/S]  28.96,53.34 90 top
V126  BCV62  [SOT143]  27.69,36.83 0 top
V127  BD140LU  [TO-126/LU]  36.58,53.34 180 top
V128  2N5551  [TO-92]  37.85,21.59 90 top
V129  BD139LU  [TO-126/LU]  56.9,53.34 180 top
V130  2N5401  [TO-92]  55.63,24.13 0 top
V131  BD140S  [TO-126/S]  64.52,53.34 90 top
V132  BD139S  [TO-126/S]  67.06,53.34 270 top
V133  BCV61  [SOT143]  65.79,34.29 180 top
V134  MJL3281A  [TO-264/LU]  82.3,101.6 0 top
V135  MJL3281A  [TO-264/LU]  82.3,96.52 180 top
V136  MJE15031  [TO-220/LU]  72.14,53.34 270 top
V137  MJE15030  [TO-220/LU]  72.14,38.1 270 top
V301  MJL1302A  [TO-264/LU]  178.82,220.98 0 top
V302  MJL1302A  [TO-264/LU]  158.5,220.98 0 top
V303  MJL3281A  [TO-264/LU]  135.64,220.98 0 top
V304  MJL3281A  [TO-264/LU]  115.32,220.98 0 top
V305  MJE15028  [TO-220/LU]  161.04,195.58 90 top
V306  MJE15029  [TO-220/LU]  140.72,182.88 270 top
V307  BC549C  [TO-92/BC]  177.55,173.99 90 top
V308  2N5401  [TO-92]  177.55,168.91 90 top
V309  2N5551  [TO-92]  172.47,168.91 0 top
V310  BC369  [SOT-54]  154.69,163.83 270 top
V311  BC549C  [TO-92/BC]  139.45,161.29 270 top
V312  2N3906  [TO-92]  134.37,168.91 0 top
V313  2N5401  [TO-92]  129.29,168.91 270 top
V314  BC559C  [TO-92/BC]  126.75,176.53 90 top
V315  2N5551  [TO-92]  124.21,168.91 0 top
V316  BC549C  [TO-92/BC]  98.81,204.47 0 top
V317  BC546B  [TO-92/BC]  106.43,201.93 90 top
V318  BC546B  [TO-92/BC]  106.43,196.85 270 top
V319  2N5401  [TO-92]  98.81,191.77 180 top
V320  MJL1302A  [TO-264/LU]  178.82,101.6 0 top
V321  MJL1302A  [TO-264/LU]  178.82,96.52 180 top
V322  MJE15030  [TO-220/LU]  168.66,53.34 270 top
V323  MJE15031  [TO-220/LU]  168.66,38.1 270 top
V324  BD140S  [TO-126/S]  163.58,53.34 270 top
V325  BD139S  [TO-126/S]  161.04,53.34 90 top
V326  BCV62  [SOT143]  162.31,34.29 180 top
V327  BD140LU  [TO-126/LU]  153.42,53.34 180 top
V328  2N5551  [TO-92]  152.15,21.59 270 top
V329  BD139LU  [TO-126/LU]  133.1,53.34 180 top
V330  2N5401  [TO-92]  134.37,24.13 90 top
V331  BD140S  [TO-126/S]  125.48,53.34 90 top
V332  BD139S  [TO-126/S]  122.94,53.34 270 top
V333  BCV61  [SOT143]  124.21,34.29 90 top
V334  MJL3281A  [TO-264/LU]  107.7,101.6 0 top
V335  MJL3281A  [TO-264/LU]  107.7,96.52 180 top
V336  MJE15031  [TO-220/LU]  117.86,53.34 90 top
V337  MJE15030  [TO-220/LU]  117.86,38.1 90 top

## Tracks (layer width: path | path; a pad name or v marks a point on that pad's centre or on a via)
+UB  (via drill 0.9 pad 1.5)
  Oben/V2 2.794: 158.5,226.06 T301.2 161.04,227.33 158.5,229.87 | 158.5,226.06 T301.1 155.96,228.6 144.53,240.03 108.97,240.03 107.7,241.3 v105.16,241.3 v102.62,241.3 v100.08,241.3 | v100.08,241.3 v97.54,241.3 v95,241.3 81.03,241.3 79.76,240.03 48.01,240.03 T101.1 T101.2 31.5,228.6 32.77,228.6 46.74,242.57 78.49,242.57 79.76,243.84 100.08,243.84 | 110.24,242.57 105.16,242.57 103.89,243.84 | 100.08,243.84 v100.08,241.3 | 100.08,243.84 103.89,243.84 | 103.89,243.84 108.97,243.84 110.24,242.57 | 158.5,229.87 145.8,242.57 110.24,242.57 | 158.5,229.87 158.5,226.06
  Oben/V2 3.302: J3.1 J3.2
  Unten/V1 2.159: 103.89,232.41 103.89,233.68 | 103.89,229.87 J3.1 101.35,229.87
  Unten/V1 2.794: 158.5,226.06 T301.2 161.04,227.33 158.5,229.87 | 158.5,226.06 T301.1 155.96,228.6 144.53,240.03 108.97,240.03 103.89,234.95 102.62,234.95 102.62,237.49 | 97.54,238.76 96.27,240.03 48.01,240.03 T101.1 T101.2 31.5,228.6 32.77,228.6 46.74,242.57 78.49,242.57 | 97.54,238.76 101.35,234.95 101.35,229.87 | 103.89,229.87 103.89,232.41 | 78.49,242.57 97.54,242.57 | 97.54,242.57 98.81,242.57 | 108.97,242.57 107.7,242.57 | 107.7,242.57 102.62,237.49 | 102.62,237.49 100.08,240.03 v100.08,241.3 98.81,242.57 | 98.81,242.57 102.62,242.57 | 102.62,242.57 107.7,242.57 | 108.97,242.57 107.7,243.84 79.76,243.84 78.49,242.57 | 108.97,242.57 145.8,242.57 158.5,229.87 | 102.62,242.57 102.62,237.49 | 97.54,238.76 97.54,242.57 | 158.5,229.87 158.5,226.06
  Unten/V1 3.302: 103.89,234.95 103.89,233.68
+UB0  (via drill 0.9 pad 1.5)
  Oben/V2 3.302: 183.9,222.25 180.09,226.06 T301.4 T301.3 166.12,220.98 163.58,220.98 163.58,222.25 169.93,228.6 178.82,228.6 | 183.9,222.25 183.9,220.98 | 183.9,223.52 178.82,228.6 | 183.9,222.25 183.9,223.52 | 183.9,223.52 183.9,226.06 181.36,228.6 178.82,228.6
  Unten/V1 1.524: v158.5,201.93 G303.2 | v158.5,201.93 C305.1 | G307.1 162.31,187.96 158.5,191.77 v158.5,201.93 | 166.12,210.82 R313.1
  Unten/V1 2.159: C305.1 161.04,208.28 | C305.1 161.04,210.82 | C305.1 159.77,207.01
  Unten/V1 2.794: 180.09,216.92 183.9,220.73 | T301.3 169.93,226.06 164.85,220.98
  Unten/V1 3.302: 161.04,212.09 161.04,210.82 161.04,208.28 162.31,209.55 164.85,209.55 | 161.04,212.09 161.04,217.17 163.58,219.71 163.58,220.98 | 167.39,220.98 171.2,224.79 T301.3 T301.4 180.09,226.06 183.9,222.25 | 163.58,220.98 V302.3 | 163.58,220.98 164.85,220.98 167.39,220.98 | 183.9,220.98 V301.3 | 169.93,212.09 180.09,212.09 | 167.39,212.09 169.93,212.09 | 164.85,209.55 166.12,210.82 167.39,212.09 | 163.58,220.98 163.58,222.25 169.93,228.6 180.09,228.6 183.9,224.79 183.9,222.25 | 183.9,220.98 183.9,222.25 | 169.93,212.09 172.47,209.55 178.82,209.55 180.09,210.82 180.09,212.09 | 180.09,212.09 180.09,216.92 | 183.9,220.73 183.9,220.98 | 161.04,212.09 167.39,212.09 | 163.58,215.9 167.39,219.71 167.39,220.98 | 167.39,212.09 163.58,215.9 | 164.85,209.55 163.58,209.55 163.58,215.9
+UB1
  Oben/V2 1.016: V107.3 12.45,172.72 8.64,168.91 8.64,156.21 12.45,152.4 17.53,152.4 20.07,149.86 20.07,147.32 25.15,152.4 30.23,152.4 31.5,153.67 R119.1
  Oben/V2 1.524: R143.1 R142.1 | R143.1 R144.2 | R144.2 R145.1 | R145.1 R146.1 | R146.1 R147.2 | R147.2 R148.2 | R148.2 R149.2 | R149.2 R150.1 | R151.2 R150.1 | R152.2 R151.2 | R153.2 R152.2 | R154.2 R153.2 | R155.2 R154.2 | R156.2 R155.2 | R157.2 R156.2 | R158.2 R157.2 | R159.2 R158.2 | R160.2 R159.2 | R161.2 R160.2 | R161.2 R162.1 32.77,85.09 34.04,85.09 36.58,87.63 35.31,86.36 34.04,86.36 R161.2 | R143.1 36.58,132.08 | C115.1 R144.2 | 36.58,124.46 R146.1 | 36.58,121.92 R147.2 | 36.58,119.38 R148.2 | C116.1 R149.2 | R151.2 36.58,111.76 | 36.58,109.22 R152.2 | R153.2 36.58,106.68 | C117.1 R154.2 | 36.58,99.06 R156.2 | R157.2 36.58,96.52 | 36.58,93.98 R158.2 | R159.2 C118.1 | C104.1 20.07,147.32 | 6.35,154.69 6.35,171.7 | G109.2 21.34,144.78 | R160.2 36.58,88.9 | 36.58,127 R145.1 | 36.58,114.3 R150.1 | R155.2 36.58,101.6
  Oben/V2 2.159: 34.04,86.36 34.04,135.89 | 34.04,135.89 34.04,138.43 | 34.04,135.89 31.5,138.43
  Oben/V2 2.794: 36.58,87.63 36.58,88.9 C118.1 36.58,93.98 36.58,96.52 36.58,99.06 36.58,101.6 C117.1 36.58,106.68 36.58,109.22 36.58,111.76 36.58,114.3 C116.1 36.58,119.38 36.58,121.92 36.58,124.46 36.58,127 C115.1 36.58,132.08 36.58,138.43 | 6.35,171.7 7.62,172.97 7.62,188.21 8.64,189.23 | 8.64,189.23 12.45,189.23 R102.2 | 18.8,147.32 21.34,144.78 23.88,142.24 26.42,142.24 27.69,140.97 34.04,140.97 36.58,138.43 | 20.07,147.32 18.8,147.32 | 18.8,147.32 16.26,149.86 11.18,149.86 6.35,154.69 | 36.58,138.43 34.04,138.43 31.5,138.43 26.42,138.43 | 26.42,138.43 25.15,139.7 22.61,139.7 14.99,147.32 9.91,147.32 5.08,152.15 5.08,187.96 3.56,187.96 | 3.56,187.96 2.54,186.94 2.54,150.88 8.64,144.78 13.72,144.78 20.07,138.43 26.42,138.43 | 3.56,187.96 4.83,189.23 8.64,189.23
  Unten/V1 1.016: R174.1 35.31,25.4 34.04,26.67 34.04,29.21 35.31,30.48 R172.1 | V107.3 R106.1
  Unten/V1 1.524: R143.1 R142.1 | R143.1 R144.2 | R144.2 R145.1 | R145.1 R146.1 | R146.1 R147.2 | R147.2 R148.2 | R148.2 R149.2 | R149.2 R150.1 | R151.2 R150.1 | R152.2 R151.2 | R153.2 R152.2 | R154.2 R153.2 | R155.2 R154.2 | R161.2 R160.2 | R160.2 R159.2 | R159.2 R158.2 | R158.2 R157.2 | R157.2 R156.2 | R156.2 R155.2 | R161.2 R162.1 34.04,83.82 G128.2 34.04,59.69 31.5,57.15 31.5,53.34 | 36.58,132.08 R143.1 | C115.1 R144.2 | 36.58,124.46 R146.1 | 36.58,121.92 R147.2 | 36.58,119.38 R148.2 | C116.1 R149.2 | R151.2 36.58,111.76 | 36.58,109.22 R152.2 | R153.2 36.58,106.68 | C117.1 R154.2 | 36.58,99.06 R156.2 | R157.2 36.58,96.52 | 36.58,93.98 R158.2 | R159.2 C118.1 | 18.8,147.32 C104.1 | 31.5,53.34 31.5,41.91 34.04,39.37 34.04,34.29 35.31,33.02 R171.1 R172.1 | MP1.1 21.34,144.78 G109.2 | 31.5,53.34 V125.2 | 36.58,88.9 R160.2 | 36.58,86.36 R161.2 | 36.58,127 R145.1 | 36.58,114.3 R150.1 | R155.2 36.58,101.6
  Unten/V1 2.159: 36.58,87.63 36.58,86.36 34.04,83.82 34.04,135.89 | 34.04,135.89 34.04,137.16 | 34.04,135.89 31.5,138.43
  Unten/V1 2.54: 4.83,189.23 6.1,190.5 11.18,190.5 12.45,189.23
  Unten/V1 2.794: 36.58,87.63 36.58,88.9 C118.1 36.58,93.98 36.58,96.52 36.58,99.06 36.58,101.6 C117.1 36.58,106.68 36.58,109.22 36.58,111.76 36.58,114.3 C116.1 36.58,119.38 36.58,121.92 36.58,124.46 36.58,127 C115.1 36.58,132.08 36.58,138.43 | 11.18,151.13 7.62,154.69 7.62,188.21 8.64,189.23 | 8.64,189.23 12.45,189.23 R102.2 | 36.58,138.43 34.04,140.97 27.69,140.97 | 27.69,140.97 25.15,140.97 22.61,143.51 | 22.61,143.51 21.34,144.78 18.8,147.32 14.99,151.13 11.18,151.13 | 3.56,187.96 2.54,186.94 2.54,155.96 | 12.45,146.05 20.07,138.43 23.88,138.43 | 12.45,146.05 5.08,153.42 | 5.08,153.42 2.54,155.96 | 32.77,138.43 36.58,138.43 | 32.77,138.43 31.5,138.43 23.88,138.43 | 23.88,138.43 11.18,151.13 | 34.04,137.16 32.77,138.43 | 12.45,146.05 8.64,146.05 2.54,152.15 2.54,155.96 | 27.69,140.97 25.15,143.51 22.61,143.51 | 4.83,187.96 3.56,187.96 | 3.56,187.96 4.83,189.23 8.64,189.23 | 5.08,153.42 4.83,187.96 | 4.83,187.96 R101.2
+UB2
  Oben/V2 1.016: V307.3 180.09,172.72 181.36,171.45 181.36,156.21 177.55,152.4 172.47,152.4 168.66,148.59 | R319.1 158.5,153.67 159.77,152.4 164.85,152.4 168.66,148.59 | C304.1 168.66,147.32 168.66,148.59
  Oben/V2 1.524: R343.1 R342.1 | R343.1 R344.2 | R345.1 R344.2 | R346.1 R345.1 | R347.2 R346.1 | R348.2 R347.2 | R349.2 R348.2 | R350.1 R349.2 | R351.2 R350.1 | R352.2 R351.2 | R353.2 R352.2 | R354.2 R353.2 | R355.2 R354.2 | R360.2 R361.2 | R359.2 R360.2 | R358.2 R359.2 | R357.2 R358.2 | R357.2 R356.2 | R356.2 R355.2 | R361.2 R362.1 157.23,85.09 154.69,85.09 153.42,86.36 | R369.1 154.69,38.1 155.96,36.83 155.96,31.75 154.69,30.48 R372.1 | R343.1 153.42,132.08 | C315.1 R344.2 | R346.1 153.42,124.46 | R347.2 153.42,121.92 | R348.2 153.42,119.38 | R349.2 C316.1 | R351.2 153.42,111.76 | R352.2 153.42,109.22 | R353.2 153.42,106.68 | R354.2 C317.1 | R356.2 153.42,99.06 | R357.2 153.42,96.52 | R358.2 153.42,93.98 | R359.2 C318.1 | R361.2 155.96,86.36 153.42,86.36 | 153.42,87.63 153.42,86.36 | 169.93,147.32 C304.1 | 183.65,150.88 183.65,154.69 183.65,172.97 | 169.93,144.78 G309.2 | R345.1 153.42,127 | R350.1 153.42,114.3 | R355.2 153.42,101.6 | R360.2 153.42,88.9
  Oben/V2 2.159: 155.96,86.36 155.96,136.65
  Oben/V2 2.54: 183.65,150.88 184.92,152.15 | 184.92,171.96 182.38,174.5
  Oben/V2 2.794: 153.42,87.63 153.42,88.9 C318.1 153.42,93.98 153.42,96.52 153.42,99.06 153.42,101.6 C317.1 153.42,106.68 153.42,109.22 153.42,111.76 153.42,114.3 C316.1 153.42,119.38 153.42,121.92 153.42,124.46 153.42,127 C315.1 153.42,132.08 153.42,138.43 154.69,139.7 | 183.65,150.88 180.09,147.32 171.2,147.32 | 184.92,152.15 184.92,171.96 184.92,187.96 186.44,187.96 | 181.36,189.23 177.55,189.23 R302.2 | 171.2,147.32 169.93,147.32 169.93,144.78 | 171.2,147.32 173.74,149.86 178.82,149.86 183.65,154.69 | 186.44,187.96 187.46,186.94 187.46,150.88 181.36,144.78 177.55,144.78 | 173.74,144.78 169.93,144.78 | 173.74,144.78 177.55,144.78 | 154.69,139.7 155.96,139.7 | 154.69,139.7 155.96,140.97 162.31,140.97 | 162.31,140.97 166.12,140.97 168.66,143.51 | 169.93,144.78 168.66,143.51 | 157.74,138.43 167.39,138.43 | 167.39,138.43 173.74,144.78 | 167.39,138.43 171.2,138.43 177.55,144.78 | 182.38,174.5 182.38,188.21 181.36,189.23 | 162.31,140.97 164.85,143.51 168.66,143.51 | 181.36,189.23 185.17,189.23 186.44,187.96
  Oben/V2 3.302: 155.96,136.65 157.74,138.43
  Unten/V1 1.016: R306.1 176.28,172.72 V307.3
  Unten/V1 1.524: 158.5,53.34 158.5,57.15 155.96,59.69 G327.2 155.96,83.82 | 158.5,53.34 158.5,41.91 154.69,38.1 R369.1 | 153.42,132.08 R343.1 | C315.1 R344.2 | R346.1 153.42,124.46 | R347.2 153.42,121.92 | R348.2 153.42,119.38 | R349.2 C316.1 | R351.2 153.42,111.76 | R352.2 153.42,109.22 | R353.2 153.42,106.68 | R354.2 C317.1 | R356.2 153.42,99.06 | R357.2 153.42,96.52 | R358.2 153.42,93.98 | R359.2 C318.1 | 155.96,83.82 R362.1 R361.2 | 153.42,86.36 153.42,87.63 | 153.42,86.36 155.96,83.82 | R343.1 R342.1 | R343.1 R344.2 | R345.1 R344.2 | R346.1 R345.1 | R347.2 R346.1 | R348.2 R347.2 | R349.2 R348.2 | R350.1 R349.2 | R351.2 R350.1 | R352.2 R351.2 | R353.2 R352.2 | R354.2 R353.2 | R355.2 R354.2 | R356.2 R355.2 | R357.2 R356.2 | R357.2 R358.2 | R358.2 R359.2 | R359.2 R360.2 | R360.2 R361.2 | C304.1 169.93,147.32 | G309.2 169.93,144.78 | R372.1 152.15,30.48 150.88,29.21 R374.1 | 158.5,53.34 V325.2 | R345.1 153.42,127 | R350.1 153.42,114.3 | R355.2 153.42,101.6 | R360.2 153.42,88.9 | R361.2 153.42,86.36
  Unten/V1 2.159: 155.96,135.89 155.96,138.43 | 155.96,83.82 155.96,135.89 | 155.96,135.89 158.5,138.43
  Unten/V1 2.54: 178.82,148.59 180.09,149.86 | 177.55,189.23 178.82,190.5 183.9,190.5 186.44,187.96
  Unten/V1 2.794: 153.42,87.63 153.42,88.9 C318.1 153.42,93.98 153.42,96.52 153.42,99.06 153.42,101.6 C317.1 153.42,106.68 153.42,109.22 153.42,111.76 153.42,114.3 C316.1 153.42,119.38 153.42,121.92 153.42,124.46 153.42,127 C315.1 153.42,132.08 153.42,135.89 | 184.92,154.69 184.92,187.96 | 180.09,149.86 184.92,154.69 | 175.01,148.59 171.2,148.59 | 177.55,148.59 175.01,148.59 | 177.55,148.59 178.82,148.59 | 171.2,148.59 169.93,147.32 169.93,144.78 168.66,143.51 | 184.92,154.69 184.92,152.15 178.82,146.05 | 181.36,189.23 182.63,189.23 | 181.36,189.23 177.55,189.23 R302.2 | 155.96,138.43 153.42,135.89 | 155.96,138.43 158.5,140.97 | 158.5,140.97 162.31,140.97 | 162.31,140.97 166.12,140.97 168.66,143.51 | 155.96,138.43 158.5,138.43 167.39,138.43 | 167.39,138.43 171.2,138.43 178.82,146.05 | 184.92,187.96 186.44,187.96 187.46,186.94 187.46,150.88 182.63,146.05 178.82,146.05 | 171.2,148.59 173.74,151.13 177.55,151.13 182.38,155.96 182.38,188.21 181.36,189.23 | 175.01,148.59 172.47,146.05 172.47,143.51 MP6.1 | 162.31,140.97 164.85,143.51 168.66,143.51 | 158.5,140.97 155.96,140.97 153.42,138.43 153.42,135.89 | 167.39,138.43 MP6.1 | MP6.1 177.55,148.59 | 184.92,187.96 R301.2
-UB  (via drill 0.9 pad 1.5)
  Oben/V2 1.778: 112.78,227.33 T302.1 112.78,224.79
  Oben/V2 2.159: J1.1 87.38,227.33 | J1.2 87.38,224.79
  Oben/V2 2.54: 106.43,222.25 106.43,223.01 | 103.89,219.71 106.43,222.25 | 106.43,219.71 106.43,222.25 | 103.89,217.17 106.43,219.71 | 106.43,219.71 106.43,217.17
  Oben/V2 2.794: 106.43,217.17 103.89,214.63 v95,214.63 v95,217.17 | 104.14,219.71 103.89,219.71 v97.54,219.71 v95,217.17 | v95,217.17 103.89,217.17 | 77.22,224.79 73.41,224.79 T102.2 73.41,227.33 87.38,227.33 | 87.38,224.79 77.22,224.79 | 77.22,224.79 T102.1 | 108.21,224.79 112.78,224.79 116.59,224.79 T302.2 116.59,227.33 112.78,227.33 107.7,227.33 106.43,226.06 106.43,223.01 108.21,224.79
  Oben/V2 3.302: 87.38,224.79 87.38,227.33
  Unten/V1 1.016: J1.2 87.38,215.9 77.22,205.74 77.22,193.04 79.76,190.5 | 79.76,190.5 R141.1 | 110.24,190.5 111.51,191.77 112.78,193.04 112.78,204.47 107.7,209.55 107.7,213.36 103.89,217.17 | R341.1 110.24,190.5 | 110.24,190.5 R340.2 | 79.76,190.5 R140.2
  Unten/V1 1.524: 105.16,226.06 91.19,226.06 | 105.16,226.06 106.43,226.06 107.7,224.79 | 105.16,219.71 105.16,226.06
  Unten/V1 1.778: J1.2 89.92,226.06 J1.1 | 83.57,224.79 87.38,220.98
  Unten/V1 2.54: 106.18,220.73 105.16,219.71 | 106.18,220.73 106.18,223.27 | 106.18,218.19 106.18,220.73
  Unten/V1 2.794: 86.11,224.79 83.57,224.79 73.41,224.79 T102.2 73.41,227.33 89.92,227.33 | 86.11,224.79 87.38,224.79 | J1.2 89.92,223.52 93.73,219.71 v97.54,219.71 103.64,219.71 | 103.64,219.71 105.16,219.71 | 112.78,227.33 107.7,227.33 106.43,226.06 | 112.78,227.33 116.59,227.33 T302.2 116.59,224.79 | 89.92,219.71 87.38,222.25 J1.2 | 89.92,219.71 92.46,217.17 v95,217.17 103.89,217.17 105.16,217.17 | 89.92,219.71 89.92,217.17 | 89.92,217.17 92.46,214.63 v95,214.63 102.62,214.63 105.16,217.17 | 89.92,217.17 87.89,219.2 87.89,223.01 J1.2 | J1.2 86.11,224.79 | 105.16,217.17 106.18,218.19 | 112.78,227.33 T302.1 | 103.64,219.71 105.92,222
  Unten/V1 3.302: 87.38,224.79 88.65,226.06 89.92,226.06 91.19,226.06 89.92,224.79 89.92,223.52 | 106.18,223.27 107.7,224.79 116.59,224.79
-UB0
  Oben/V2 1.778: G119.1 82.3,218.44 79.76,220.98
  Oben/V2 3.302: T102.3 T102.4 56.9,224.79 59.44,222.25 | T102.3 59.44,226.06 59.44,222.25 | 59.44,222.25 60.71,220.98 61.98,222.25 T102.3
  Unten/V1 1.524: 83.57,216.15 84.84,217.42 G119.1 | R121.2 56.9,195.58 53.09,195.58 G110.2 50.55,207.01 C108.2
  Unten/V1 1.778: 83.57,218.44 G119.1
  Unten/V1 2.159: 69.6,214.63 64.52,219.71
  Unten/V1 2.794: 79.76,214.63 83.57,218.44
  Unten/V1 3.302: T102.3 T102.4 | 59.44,212.09 59.44,218.44 | 79.76,220.98 79.76,214.63 77.22,212.09 73.41,212.09 | 79.76,220.98 V104.3 | 59.44,218.44 61.98,218.44 63.25,219.71 | 63.25,219.71 64.52,219.71 61.98,222.25 T102.3 | 73.41,212.09 70.87,214.63 69.6,214.63 68.33,214.63 65.79,212.09 | C108.2 50.55,209.55 55.63,209.55 | 55.63,209.55 58.17,212.09 59.44,212.09 | 59.44,220.98 V103.3 | 59.44,218.44 59.44,220.98 | 59.44,220.98 59.44,226.06 T102.3 | T102.3 63.25,226.06 63.25,219.71 | 73.41,212.09 73.41,209.55 76.97,209.55 83.57,216.15 | 65.79,212.09 59.44,212.09 | 55.63,209.55 65.79,209.55 65.79,212.09 | 79.76,220.98 81.03,220.98 83.57,218.44
-UB1
  Oben/V2 1.016: V112.3 69.6,172.72 70.87,171.45 70.87,156.21 C114.2
  Oben/V2 1.524: R204.2 R203.2 | R204.2 R205.2 | R205.2 R206.1 | R206.1 R207.2 | R207.2 R208.1 | R208.1 R209.2 | R209.2 R210.1 | R210.1 R211.1 | R211.1 R212.1 | R212.1 R213.2 | R213.2 R214.2 | R215.2 R214.2 | R216.2 R215.2 | R217.2 R216.2 | R218.2 R217.2 | R219.2 R218.2 | R220.2 R219.2 | R221.2 R220.2 | R222.2 R221.2 | R222.2 R223.2 60.71,85.09 59.44,85.09 56.9,87.63 58.17,86.36 59.44,86.36 R222.2 | C129.2 R220.2 | R219.2 56.9,93.98 | 56.9,96.52 R218.2 | R217.2 56.9,99.06 | R215.2 C128.2 | 56.9,106.68 R214.2 | 56.9,109.22 R213.2 | 56.9,111.76 R212.1 | C127.2 R210.1 | 56.9,119.38 R209.2 | 56.9,121.92 R208.1 | 56.9,124.46 R207.2 | C126.2 R205.2 | R204.2 56.9,132.08 | 73.41,173.99 73.41,154.94 65.79,147.32 | C114.2 64.52,147.32 | G118.1 61.98,144.78 | R221.2 56.9,88.9 | 56.9,127 R206.1 | 56.9,114.3 R211.1 | 56.9,101.6 R216.2
  Oben/V2 2.159: 59.44,137.16 59.44,86.36
  Oben/V2 2.794: 56.9,87.63 56.9,88.9 C129.2 56.9,93.98 56.9,96.52 56.9,99.06 56.9,101.6 C128.2 56.9,106.68 56.9,109.22 56.9,111.76 56.9,114.3 C127.2 56.9,119.38 56.9,121.92 56.9,124.46 56.9,127 C126.2 56.9,132.08 56.9,134.62 | 72.14,151.13 72.14,143.51 | 56.9,134.62 59.44,137.16 | 59.44,137.16 59.44,139.7 60.71,140.97 61.98,140.97 65.79,144.78 | 65.79,144.78 69.6,144.78 77.22,152.4 | 65.79,147.32 64.52,147.32 61.98,144.78 60.71,143.51 59.44,143.51 56.9,140.97 56.9,134.62 | 77.22,156.21 77.22,186.69 74.68,189.23 70.87,189.23 | 77.22,156.21 77.22,152.4 | 77.22,152.4 77.22,148.59 72.14,143.51 | 59.44,137.16 60.71,138.43 63.25,138.43 67.06,142.24 70.87,142.24 72.14,143.51 | 73.41,173.99 72.14,175.26 72.14,187.96 70.87,189.23 | 70.87,189.23 65.79,189.23 R125.1 | 74.68,153.67 77.22,156.21 | 74.68,153.67 72.14,151.13 | 72.14,151.13 65.79,144.78 | R127.1 74.68,153.67
  Unten/V1 1.016: V112.3 64.52,172.72 R122.2
  Unten/V1 1.524: R222.2 R223.2 59.44,83.82 G131.1 59.44,59.69 61.98,57.15 61.98,53.34 | R222.2 R221.2 | R221.2 R220.2 | R220.2 R219.2 | R219.2 R218.2 | R218.2 R217.2 | R217.2 R216.2 | R216.2 R215.2 | R215.2 R214.2 | R213.2 R214.2 | R212.1 R213.2 | R211.1 R212.1 | R210.1 R211.1 | R209.2 R210.1 | R208.1 R209.2 | R207.2 R208.1 | R206.1 R207.2 | R205.2 R206.1 | R204.2 R205.2 | R204.2 R203.2 | 56.9,132.08 R204.2 | C126.2 R205.2 | 56.9,124.46 R207.2 | 56.9,121.92 R208.1 | 56.9,119.38 R209.2 | C127.2 R210.1 | 56.9,111.76 R212.1 | 56.9,109.22 R213.2 | 56.9,106.68 R214.2 | R215.2 C128.2 | R217.2 56.9,99.06 | 56.9,96.52 R218.2 | R219.2 56.9,93.98 | C129.2 R220.2 | 63.25,146.05 C114.2 | 58.17,38.1 59.44,36.83 59.44,29.21 58.17,27.94 R197.2 | 63.25,144.78 G118.1 | 61.98,53.34 V131.2 | 61.98,53.34 61.98,41.91 58.17,38.1 | 58.17,38.1 R193.2 55.63,38.1 54.36,36.83 R192.2 | R221.2 56.9,88.9 | 56.9,86.36 R222.2 | 56.9,127 R206.1 | 56.9,114.3 R211.1 | 56.9,101.6 R216.2
  Unten/V1 2.159: 59.44,137.16 59.44,83.82 56.9,86.36 56.9,87.63
  Unten/V1 2.54: 65.79,189.23 67.06,190.5 73.41,190.5 74.68,189.23
  Unten/V1 2.794: 56.9,87.63 56.9,88.9 C129.2 56.9,93.98 56.9,96.52 56.9,99.06 56.9,101.6 C128.2 56.9,106.68 56.9,109.22 56.9,111.76 56.9,114.3 C127.2 56.9,119.38 56.9,121.92 56.9,124.46 56.9,127 C126.2 56.9,132.08 56.9,134.62 | 65.79,189.23 72.14,189.23 | 72.14,189.23 74.68,189.23 R127.1 75.95,186.69 75.95,185.42 | 56.9,134.62 59.44,137.16 59.44,139.7 60.71,140.97 63.25,140.97 MP2.1 64.52,140.97 | 70.87,154.94 70.87,144.78 69.6,143.51 64.52,143.51 64.52,140.97 | 65.79,189.23 68.33,189.23 70.87,186.69 70.87,154.94 | 56.9,138.43 56.9,140.97 59.44,143.51 61.98,143.51 63.25,144.78 63.25,146.05 68.33,146.05 70.87,148.59 70.87,154.94 | 56.9,138.43 56.9,134.62 | 64.52,140.97 70.87,140.97 73.41,143.51 73.41,187.96 | 73.41,187.96 75.95,185.42 | 75.95,185.42 75.95,142.24 72.14,138.43 56.9,138.43 | 65.79,189.23 R125.1 | 72.14,189.23 73.41,187.96
-UB2
  Oben/V2 1.016: R322.2 V314.3 121.67,175.26 119.13,172.72 119.13,157.48 128.02,148.59 C314.2 128.02,144.78
  Oben/V2 1.524: R422.2 R423.2 129.29,85.09 131.83,85.09 133.1,86.36 | R421.2 R422.2 | R420.2 R421.2 | R419.2 R420.2 | R418.2 R419.2 | R417.2 R418.2 | R416.2 R417.2 | R415.2 R416.2 | R414.2 R415.2 | R413.2 R414.2 | R412.1 R413.2 | R411.1 R412.1 | R410.1 R411.1 | R409.2 R410.1 | R408.1 R409.2 | R407.2 R408.1 | R406.1 R407.2 | R406.1 R405.2 | R405.2 R404.2 | R404.2 R403.2 | 133.1,86.36 130.56,86.36 R422.2 | R420.2 C330.2 | R419.2 133.1,93.98 | R418.2 133.1,96.52 | R417.2 133.1,99.06 | R415.2 C329.2 | R414.2 133.1,106.68 | R413.2 133.1,109.22 | R412.1 133.1,111.76 | R410.1 C328.2 | R409.2 133.1,119.38 | R408.1 133.1,121.92 | R407.2 133.1,124.46 | R405.2 C327.2 | R404.2 133.1,132.08 | 133.1,87.63 133.1,86.36 | 116.59,175.26 116.59,156.21 116.59,153.67 | R406.1 133.1,127 | R411.1 133.1,114.3 | R416.2 133.1,101.6 | R421.2 133.1,88.9
  Oben/V2 1.778: G318.1 134.37,143.51 130.56,143.51 | 126.75,142.24 MP4.1
  Oben/V2 2.159: 130.56,138.43 130.56,135.89 | 130.56,86.36 130.56,135.89 | 128.02,138.43 130.56,135.89
  Oben/V2 2.794: 133.1,87.63 133.1,88.9 C330.2 133.1,93.98 133.1,96.52 133.1,99.06 133.1,101.6 C329.2 133.1,106.68 133.1,109.22 133.1,111.76 133.1,114.3 C328.2 133.1,119.38 133.1,121.92 133.1,124.46 133.1,127 C327.2 133.1,132.08 133.1,140.97 130.56,143.51 129.29,143.51 128.02,144.78 125.48,147.32 | 115.32,153.67 116.59,153.67 122.94,147.32 125.48,147.32 | 115.32,175.26 115.32,153.67 | 115.32,175.26 116.59,175.26 117.86,176.53 117.86,186.69 | 125.48,147.32 116.59,156.21 | 120.4,189.23 124.21,189.23 R325.1 | 112.78,153.67 112.78,186.69 115.32,189.23 116.59,189.23 | 115.32,153.67 112.78,153.67 | 115.32,153.67 115.32,151.13 121.67,144.78 | 121.67,144.78 124.21,144.78 126.75,142.24 128.02,140.97 129.29,140.97 130.56,139.7 130.56,138.43 128.02,138.43 126.75,138.43 122.94,142.24 121.67,142.24 | 121.67,144.78 121.67,142.24 | 117.86,186.69 120.4,189.23 | 121.67,142.24 120.4,142.24 112.78,149.86 112.78,153.67 | 120.4,189.23 116.59,189.23 | 117.86,186.69 119.13,187.96 | 116.59,189.23 R326.1 115.32,175.26
  Unten/V1 1.016: R396.2 R395.2 134.37,33.02 135.64,34.29 R392.2
  Unten/V1 1.524: 130.56,83.82 G331.1 130.56,59.69 128.02,57.15 128.02,53.34 | R404.2 133.1,132.08 | R405.2 C327.2 | R407.2 133.1,124.46 | R408.1 133.1,121.92 | R409.2 133.1,119.38 | R410.1 C328.2 | R412.1 133.1,111.76 | R413.2 133.1,109.22 | R414.2 133.1,106.68 | R415.2 C329.2 | R417.2 133.1,99.06 | R418.2 133.1,96.52 | R419.2 133.1,93.98 | R420.2 C330.2 | 133.1,86.36 133.1,87.63 | R422.2 133.1,86.36 | 130.56,83.82 R423.2 R422.2 | R404.2 R403.2 | R405.2 R404.2 | R406.1 R405.2 | R406.1 R407.2 | R407.2 R408.1 | R408.1 R409.2 | R409.2 R410.1 | R410.1 R411.1 | R411.1 R412.1 | R412.1 R413.2 | R413.2 R414.2 | R414.2 R415.2 | R415.2 R416.2 | R416.2 R417.2 | R417.2 R418.2 | R418.2 R419.2 | R419.2 R420.2 | R420.2 R421.2 | R421.2 R422.2 | R395.2 131.83,33.02 130.56,34.29 130.56,39.37 128.02,41.91 128.02,53.34 | 128.02,53.34 V331.2 | R406.1 133.1,127 | R411.1 133.1,114.3 | R416.2 133.1,101.6 | R421.2 133.1,88.9 | 130.56,83.82 133.1,86.36
  Unten/V1 1.778: G318.1 134.37,143.51 130.56,143.51
  Unten/V1 2.159: 130.56,83.82 130.56,135.89 130.56,138.43
  Unten/V1 2.794: 133.1,87.63 133.1,88.9 C330.2 133.1,93.98 133.1,96.52 133.1,99.06 133.1,101.6 C329.2 133.1,106.68 133.1,109.22 133.1,111.76 133.1,114.3 C328.2 133.1,119.38 133.1,121.92 133.1,124.46 133.1,127 C327.2 133.1,132.08 133.1,140.97 130.56,143.51 124.21,143.51 | 116.59,154.94 116.59,187.96 R326.1 | 121.67,143.51 121.67,146.05 | 121.67,146.05 121.67,149.86 | 121.67,149.86 121.67,153.67 119.13,156.21 119.13,187.96 | 121.67,149.86 116.59,154.94 | 116.59,154.94 116.59,152.4 | 121.67,143.51 119.13,146.05 119.13,149.86 116.59,152.4 | 124.21,143.51 121.67,143.51 | 116.59,152.4 114.05,154.94 | 116.59,152.4 116.59,146.05 | 116.59,146.05 116.59,144.78 120.4,140.97 129.29,140.97 130.56,139.7 130.56,138.43 | 116.59,146.05 114.05,143.51 | 114.05,143.51 119.13,138.43 128.02,138.43 130.56,135.89 | 114.05,154.94 114.05,143.51 | 119.13,187.96 120.4,189.23 124.21,189.23 | R326.1 119.13,187.96 | R326.1 117.86,190.5 | 117.86,190.5 124.21,190.5 125.48,189.23 R325.1 | 114.05,154.94 114.05,187.96 116.59,190.5 117.86,190.5 | 124.21,143.51 121.67,146.05
MASSE  (via drill 0.9 pad 1.5)
  Oben/V2 1.016: G122.1 87.63,187.96 83.57,183.9 J105.2 | G322.1 101.35,187.96 103.89,185.42 104.91,185.42 106.43,183.9 J305.2
  Oben/V2 1.524: 165.61,147.32 C304.2 | 131.07,147.32 C314.1 | 58.93,147.32 C114.1 | C104.2 25.15,147.32 | 30.23,147.32 27.69,147.32 | v36.58,71.12 36.58,62.23 37.85,60.96 40.14,60.96 41.66,59.44 41.66,57.15 C121.1 | v56.9,71.12 56.9,67.31 60.71,63.5 v69.6,63.5 | R165.2 31.25,48.26 33.28,50.29 41.15,50.29 R183.1 | v153.42,71.12 153.42,67.31 157.23,63.5 v166.12,63.5 | C321.1 138.18,57.15 138.18,59.44 136.66,60.96 134.37,60.96 133.1,62.23 v133.1,63.5 | R426.1 127.77,48.26 129.8,50.29 137.67,50.29 R383.1 | 95,208.28 v95,162.56 | 95,209.55 95,208.28 | 95,208.28 G320.1 G120.1 92.46,209.55
  Oben/V2 1.778: 159.26,147.32 162.31,147.32 | 136.91,147.32 134.37,147.32 | 53.09,147.32 55.63,147.32 | 35.31,173.99 C106.2 35.31,168.91 | 42.93,173.99 C109.1 42.93,168.91 | 147.07,173.99 C309.1 147.07,168.91 | 154.69,173.99 C306.2 154.69,168.91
